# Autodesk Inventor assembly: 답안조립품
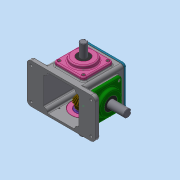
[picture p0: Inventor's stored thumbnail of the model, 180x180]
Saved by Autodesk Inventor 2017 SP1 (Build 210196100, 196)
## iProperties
Part Number: 답안조립품
Material: 일반
Document SubType Name: Assembly
Designer: MRC
Author: MRC
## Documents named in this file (16)
- C:\Users\MRC\Desktop\620307V1006\답안조립품.iam
- C:\Users\MRC\Desktop\620307V1006\본체.ipt
- C:\Users\MRC\Desktop\620307V1006\개스킷.ipt
- C:\Users\MRC\Desktop\620307V1006\메인베벨기어.ipt
- C:\Users\MRC\Desktop\620307V1006\메인축.ipt
- C:\Users\MRC\Desktop\620307V1006\메인커버.ipt
- C:\Users\MRC\Desktop\620307V1006\베어링 6203.ipt
- C:\Users\MRC\Desktop\620307V1006\베어링 6204.ipt
- C:\Users\MRC\Desktop\620307V1006\볼트 M4.ipt
- C:\Users\MRC\Desktop\620307V1006\상부커버.ipt
- C:\Users\MRC\Desktop\620307V1006\서브베벨기어.ipt
- C:\Users\MRC\Desktop\620307V1006\서브축.ipt
- C:\Users\MRC\Desktop\620307V1006\서브커버.ipt
- C:\Users\MRC\Desktop\620307V1006\오일 실 17 32 8.ipt
- C:\Users\MRC\Desktop\620307V1006\오일 실 20 35 8.ipt
- C:\Users\MRC\Desktop\620307V1006\키 4x4.ipt
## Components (1 placed, 1 different names)
1. 개스킷:1
## Named parameters: d26_d15 = 0, d27_d16 = 0, d28_d17 = 0, d29_d18 = 0, d30_d19 = 0, d31_d20 = 0, d32_d21 = 0, d33_d22 = 0, d34_d23 = 0, d35_d24 = 0, d36_d25 = 0
